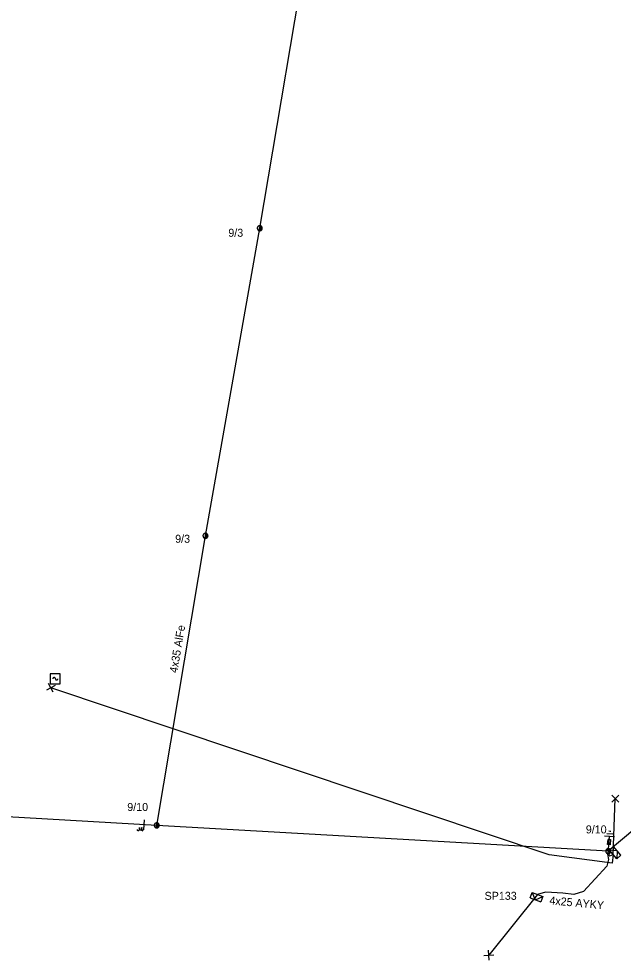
# Model space of a CAD drawing. Extents: x -788458 to -786145, y -1154772 to -1152372.
# Drawn here: x -786600.5 to -786525, y -1153563.6 to -1153446 of the extents above; entities that cross this region are included whole.
import ezdxf

# ---------------------------------------------------------------- set-up
doc = ezdxf.new("R2010")
doc.units = 0
for name, color, linetype in [('Vrstva 1', 7, 'Continuous'), ('Vrstva 12', 7, 'Continuous'), ('Vrstva 13', 7, 'Continuous'), ('Vrstva 14', 7, 'Continuous'), ('Vrstva 15', 7, 'Continuous'), ('Vrstva 16', 7, 'Continuous'), ('Vrstva 18', 7, 'Continuous'), ('Vrstva 2', 7, 'Continuous'), ('Vrstva 31', 7, 'Continuous'), ('Vrstva 33', 7, 'Continuous'), ('Vrstva 34', 7, 'Continuous'), ('Vrstva 4', 7, 'Continuous'), ('Vrstva 52', 7, 'Continuous'), ('Vrstva 54', 7, 'Continuous'), ('Vrstva 59', 7, 'Continuous'), ('Vrstva 9', 7, 'Continuous')]:
    doc.layers.add(name, color=color, linetype=linetype)

# ---------------------------------------------------------------- blocks, each defined once
blk = doc.blocks.new('NN440')
at = {"layer": 'Vrstva 2'}
for points in [[(0.63, 0), (0.63, 0.06), (0.62, 0.13), (0.6, 0.19), (0.58, 0.25), (0.55, 0.31), (0.51, 0.37), (0.47, 0.42), (0.42, 0.46), (0.37, 0.51), (0.32, 0.54), (0.26, 0.57), (0.2, 0.59), (0.13, 0.61), (0.07, 0.62), (0, 0.63), (-0.06, 0.62), (-0.13, 0.61), (-0.19, 0.59), (-0.26, 0.57), (-0.31, 0.54), (-0.37, 0.51), (-0.42, 0.46), (-0.47, 0.42), (-0.51, 0.37), (-0.54, 0.31), (-0.57, 0.25), (-0.6, 0.19), (-0.62, 0.13), (-0.63, 0.06), (-0.63, 0), (-0.63, -0.07), (-0.62, -0.14), (-0.6, -0.2), (-0.57, -0.26), (-0.54, -0.32), (-0.51, -0.37), (-0.47, -0.43), (-0.42, -0.47), (-0.37, -0.51), (-0.31, -0.55), (-0.26, -0.58), (-0.19, -0.6), (-0.13, -0.62), (-0.06, -0.63), (0, -0.63), (0.07, -0.63), (0.13, -0.62), (0.2, -0.6), (0.26, -0.58), (0.32, -0.55), (0.37, -0.51), (0.42, -0.47), (0.47, -0.43), (0.51, -0.37), (0.55, -0.32), (0.58, -0.26), (0.6, -0.2), (0.62, -0.14), (0.63, -0.07), (0.63, 0)], [(-0.63, 0), (0.63, 0)], [(-0.6, -0.18), (0.57, -0.18)], [(-0.51, -0.32), (0.5, -0.32)], [(-0.37, -0.47), (0.35, -0.47)]]:
    blk.add_lwpolyline(points, dxfattribs=at)
blk = doc.blocks.new('NN840')
at = {"layer": 'Vrstva 15'}
for points in [[(0, 0.62), (0, -0.63)], [(-0.75, -0.71), (-0.75, -0.66)], [(-0.73, -0.76), (-0.75, -0.71)], [(-0.66, -0.8), (-0.73, -0.76)], [(-0.63, -0.8), (-0.66, -0.8)], [(-0.56, -0.76), (-0.63, -0.8)], [(-0.54, -0.71), (-0.56, -0.76)], [(-0.54, -0.38), (-0.54, -0.71)], [(-0.33, -0.38), (-0.33, -0.8)], [(-0.33, -0.64), (-0.13, -0.38)], [(-0.26, -0.56), (-0.09, -0.8)]]:
    blk.add_lwpolyline(points, dxfattribs=at)
blk = doc.blocks.new('NN800')
at = {"layer": 'Vrstva 1'}
for points in [[(-0.44, 0.44), (0.44, -0.44)], [(-0.44, -0.44), (0.44, 0.44)]]:
    blk.add_lwpolyline(points, dxfattribs=at)
blk = doc.blocks.new('NN820')
at = {"layer": 'Vrstva 13'}
for points in [[(0, 0), (0, -1.05)], [(-0.16, -0.81), (0.16, -0.81)], [(-0.16, -1.47), (-0.16, -0.81)], [(0, -1.05), (-0.06, -0.93)], [(0, -1.05), (0.06, -0.93)], [(0.16, -0.81), (0.16, -1.47)], [(0.16, -1.47), (-0.16, -1.47)], [(0, -1.47), (0, -1.87)]]:
    blk.add_lwpolyline(points, dxfattribs=at)
blk = doc.blocks.new('NN630')
at = {"layer": 'Vrstva 9'}
for points in [[(0, -0.7), (-0.7, 0)], [(-0.7, -0.7), (-0.7, 0), (0.7, 0), (0.7, -0.7)], [(-0.7, -0.7), (0.7, -0.7)], [(0, -0.7), (0.7, 0)]]:
    blk.add_lwpolyline(points, dxfattribs=at)
blk = doc.blocks.new('NN810')
at = {"layer": 'Vrstva 14'}
for points in [[(0, -0.64), (0, -1.89)], [(0.63, -1.89), (-0.62, -1.89)], [(0.39, -2.2), (-0.4, -2.2)], [(0, -2.52), (-0.12, -2.52)], [(0.14, -2.52), (0, -2.52)]]:
    blk.add_lwpolyline(points, dxfattribs=at)
blk = doc.blocks.new('NN740')
at = {"layer": 'Vrstva 1'}
for points in [[(0.62, 0.62), (-0.63, 0.62)], [(-0.63, 0.62), (-0.63, -0.63)], [(0, 0), (0, 0.01), (0, 0.03), (-0.01, 0.05), (-0.01, 0.06), (-0.02, 0.08), (-0.03, 0.09), (-0.04, 0.1), (-0.05, 0.11), (-0.06, 0.12), (-0.08, 0.13), (-0.09, 0.14), (-0.11, 0.14), (-0.12, 0.15), (-0.14, 0.15), (-0.15, 0.15), (-0.17, 0.15), (-0.18, 0.15), (-0.2, 0.15), (-0.21, 0.14), (-0.23, 0.13), (-0.24, 0.12), (-0.26, 0.11), (-0.27, 0.1), (-0.28, 0.09), (-0.29, 0.08), (-0.29, 0.06), (-0.3, 0.05), (-0.3, 0.03), (-0.31, 0.02), (-0.31, 0), (-0.31, 0)], [(0.62, -0.63), (0.62, 0.62)], [(-0.63, -0.63), (0.62, -0.63)], [(0, 0), (0, -0.02), (0, -0.03), (0.01, -0.05), (0.01, -0.06), (0.02, -0.08), (0.03, -0.09), (0.04, -0.1), (0.05, -0.11), (0.06, -0.12), (0.07, -0.13), (0.09, -0.14), (0.1, -0.15), (0.12, -0.15), (0.13, -0.15), (0.15, -0.15), (0.16, -0.15), (0.18, -0.15), (0.19, -0.15), (0.21, -0.14), (0.22, -0.14), (0.24, -0.13), (0.25, -0.12), (0.26, -0.11), (0.27, -0.09), (0.28, -0.08), (0.29, -0.07), (0.29, -0.05), (0.3, -0.04), (0.3, -0.02), (0.3, -0.01), (0.3, -0.01)]]:
    blk.add_lwpolyline(points, dxfattribs=at)

msp = doc.modelspace()

# ---------------------------------------------------------------- linework, layer by layer
at = {"layer": 'Vrstva 1'}
msp.add_lwpolyline([(-786489.69, -1153518.84), (-786509.16, -1153535.21), (-786526.82, -1153550.01), (-786583.29, -1153546.79), (-786577.19, -1153510.6), (-786570.4, -1153472.16), (-786563.85, -1153433.39), (-786557.73, -1153395.36), (-786551.92, -1153358.3), (-786545.97, -1153321.74)], dxfattribs=at)
at = {"layer": 'Vrstva 4'}
msp.add_lwpolyline([(-786583.29, -1153546.79), (-786630.06, -1153544.09), (-786683.21, -1153541.41), (-786728.17, -1153546.54), (-786775.96, -1153550.46), (-786776.21, -1153554.45)], dxfattribs=at)
at = {"layer": 'Vrstva 52'}
for points in [[(-786526.82, -1153550.01), (-786526.9, -1153550.37), (-786526.78, -1153551.05), (-786526.99, -1153551.9), (-786529.92, -1153555.04), (-786531.13, -1153555.44), (-786532.51, -1153555.25), (-786533.91, -1153555.18), (-786534.67, -1153555.15), (-786535.67, -1153555.44)], [(-786526.82, -1153550.01), (-786526.65, -1153550.18), (-786526.75, -1153550.49), (-786526.63, -1153550.59), (-786526.22, -1153550.43)]]:
    msp.add_lwpolyline(points, dxfattribs=at)
at = {"layer": 'Vrstva 59'}
for points in [[(-786526.22, -1153550.43), (-786526.32, -1153551.5), (-786534.23, -1153550.48), (-786596.53, -1153529.61)], [(-786526.22, -1153550.43), (-786525.94, -1153543.45)], [(-786535.67, -1153555.44), (-786541.76, -1153563.01)]]:
    msp.add_lwpolyline(points, dxfattribs=at)

# ---------------------------------------------------------------- block references
at = {"layer": 'Vrstva 13'}
for p, xscale, yscale, rotation in [((-786570.4, -1153472.16), 0.5, 0.49999999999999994, 79.82726393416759), ((-786577.19, -1153510.6), 0.5, 0.5000000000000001, 79.82752495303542), ((-786583.29, -1153546.79), 0.5000000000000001, 0.5, 79.82700001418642), ((-786526.82, -1153550.01), 0.49999999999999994, 0.49999999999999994, 175.12867489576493)]:
    msp.add_blockref('NN440', p, dxfattribs=dict(at, xscale=xscale, yscale=yscale, rotation=rotation))
at = {"layer": 'Vrstva 15', "rotation": 175.12867489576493}
msp.add_blockref('NN810', (-786526.82, -1153550.01), dxfattribs=at)
at = {"layer": 'Vrstva 16', "rotation": 175.12867489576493}
msp.add_blockref('NN820', (-786526.82, -1153550.01), dxfattribs=at)
at = {"layer": 'Vrstva 18', "rotation": -3.303979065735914}
msp.add_blockref('NN840', (-786584.9, -1153546.7), dxfattribs=at)
at = {"layer": 'Vrstva 31'}
for p, rotation in [((-786526.22, -1153550.43), 131.18592516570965), ((-786535.67, -1153555.44), -20.888980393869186)]:
    msp.add_blockref('NN630', p, dxfattribs=dict(at, rotation=rotation))
at = {"layer": 'Vrstva 34'}
msp.add_blockref('NN740', (-786595.96, -1153528.46), dxfattribs=at)
for p, rotation in [((-786596.53, -1153529.61), 163.44677778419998), ((-786525.94, -1153543.45), -91.74810834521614), ((-786541.76, -1153563.01), 50.22537782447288)]:
    msp.add_blockref('NN800', p, dxfattribs=dict(at, rotation=rotation))

# ---------------------------------------------------------------- texts
at = {"layer": 'Vrstva 12'}
for s, p in [('9/3', (-786574.33, -1153473.23)), ('9/3', (-786580.98, -1153511.47)), ('9/10', (-786586.97, -1153544.99)), ('9/10', (-786529.63, -1153547.79))]:
    msp.add_text(s, height=1, dxfattribs=at).set_placement(p)
at = {"layer": 'Vrstva 2'}
msp.add_text('4x35 AlFe', height=1, rotation=80.432, dxfattribs=at).set_placement((-786580.72, -1153527.79))
at = {"layer": 'Vrstva 33'}
msp.add_text('SP133', height=1, dxfattribs=at).set_placement((-786542.29, -1153556.09))
at = {"layer": 'Vrstva 54'}
msp.add_text('4x25 AYKY', height=1, rotation=354.695, dxfattribs=at).set_placement((-786534.22, -1153556.64))

doc.saveas('drawing.dxf')
